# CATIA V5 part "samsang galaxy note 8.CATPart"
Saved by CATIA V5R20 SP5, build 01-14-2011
Part number: Part1
Material "Black": density 7860 kg/m3, Young's modulus 2e+11 Pa, Poisson ratio 0.266
Bounding box of the stored display mesh (mm): x -4.4 to 4.3, y -38.2 to 38.2, z -81.25 to 81.25
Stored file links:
  E:\180212220\创新作业180212220\samsang galaxy note 8.CATPart
  C:\Program Files\Dassault Systemes\B20\intel_a\startup\materials\Catalog.CATMaterial
  C:\Program Files\Dassault Systemes\B20\intel_a\startup\materials\black_env_512x512.jpg
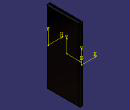
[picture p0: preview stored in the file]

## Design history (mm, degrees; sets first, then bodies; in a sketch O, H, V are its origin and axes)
Body1 (main body), material "Black"
  Sketch1 on yz-plane, origin (0, 0, 0), H (0, 1, 0), V (0, 0, 1)
    line L1 (37.4, 81.25) -> (37.4, -81.25)
    line L2 (37.4, -81.25) -> (-37.4, -81.25)
    line L3 (-37.4, -81.25) -> (-37.4, 81.25)
    line L4 (-37.4, 81.25) -> (37.4, 81.25)
    length L4 = 74.8
    length L1 = 162.5
    vertical: L1 V, L3 V
    horizontal: L2 H, L4 H
    equidistance: L1 L3 O, L2 L4 O
  Pad1: profile Sketch1, direction (1, 0, 0), length 4.3, mirrored extent
  Fillet1: radius 2.5, on end face of Pad1; face of Pad1 from Sketch1.L1; start face of Pad1; face of Pad1 from Sketch1.L3
  Plane1: type Offset, RefPlane yz-plane, Offset 4.3
  Plane2: type Offset, RefPlane yz-plane, Offset 4.3, reversed
  Plane3: type Offset, RefPlane zx-plane, Offset 37.4
  Plane4: type Offset, RefPlane zx-plane, Offset 37.4, reversed
  Plane5: type Offset, RefPlane xy-plane, Offset 81.25
  Plane6: type Offset, RefPlane xy-plane, Offset 81.25, reversed
  Sketch2 on Plane6, origin (0, 0, -81.25), H (1, 0, 0), V (0, 1, 0)
    construction line L1 (0, 2.9) -> (0, -2.9)
    point P1 (0, 2.9)
    line L2 (1.25, 2.9) -> (1.25, -2.9)
    line L3 (-1.25, -2.9) -> (-1.25, 2.9)
    arc A1 centre (0, -2.9) radius 1.25 from (1.25, -2.9) to (-1.25, -2.9) cw
    arc A2 centre (0, 2.9) radius 1.25 from (-1.25, 2.9) to (1.25, 2.9) cw
    line L4 (0.5, 2.5) -> (0.5, -2.5)
    line L5 (0.5, -2.5) -> (-0.5, -2.5)
    line L6 (-0.5, -2.5) -> (-0.5, 2.5)
    line L7 (-0.5, 2.5) -> (0.5, 2.5)
    distance P1 H = 2.9
    length L1 = 5.8
    distance L1 L2 = 1.25
    length L7 = 1
    length L4 = 5
    coincidence: P1 V
    vertical: L1 V, L4 V, L6 V
    tangency: A1 L2, A2 L2, A1 L3, A2 L3
    horizontal: L5 H, L7 H
    equidistance: L4 L6 O, L5 L7 O
  Pocket1: profile Sketch2, direction (0, 0, 1), length 6
  Sketch3 on Plane1, origin (4.3, 0, 0), H (0, 1, 0), V (0, 0, 1)
    construction line L1 (-3.5, 75) -> (3.5, 75)
    point P1 (-3.5, 75)
    line L2 (-3.5, 75.5) -> (3.5, 75.5)
    line L3 (3.5, 74.5) -> (-3.5, 74.5)
    arc A1 centre (3.5, 75) radius 0.5 from (3.5, 75.5) to (3.5, 74.5) cw
    arc A2 centre (-3.5, 75) radius 0.5 from (-3.5, 74.5) to (-3.5, 75.5) cw
    circle A3 centre (15, 75) radius 1.5
    point P7 (15, 75)
    circle A4 centre (20, 75) radius 1
    point P8 (20, 75)
    distance P1 V = 3.5
    distance P1 H = 75
    length L1 = 7
    distance L1 L2 = 0.5
    distance P7 H = 75
    distance P7 V = 15
    radius A3 = 1.5
    distance P8 H = 75
    radius A4 = 1
    horizontal: L1 H
    tangency: A1 L2, A2 L2, A1 L3, A2 L3
  Pocket2: profile Sketch3, direction (-1, 0, 0), length 0.2
  Plane7: type Offset, RefPlane Plane6, Offset 5
  Sketch4 on Plane6, origin (0, 0, -81.25), H (1, 0, 0), V (0, 1, 0)
    circle A1 centre (0, -25) radius 1.75
    point P1 (0, -25)
    distance P1 V = 0
    distance P1 H = 25
    radius A1 = 1.75
  Sketch5 on Plane7, origin (0, 0, -76.25), H (1, 0, 0), V (0, 1, 0)
    circle A1 centre (0, -25) radius 1.05
    point P1 (0, -25)
    distance P1 V = 0
    distance P1 H = 25
    radius A1 = 1.05
  Pocket3: profile Sketch4, direction (0, 0, 1), length 5
  Pocket4: profile Sketch5, direction (0, 0, 1), length 3
  Sketch6 on Plane3, origin (0, 37.4, 0), H (-1, 0, 0), V (0, 0, 1)
    construction line L1 (0, 20) -> (0, 28)
    point P1 (0, 20)
    line L2 (-0.6, 20) -> (-0.6, 28)
    line L3 (0.6, 28) -> (0.6, 20)
    arc A1 centre (0, 28) radius 0.6 from (-0.6, 28) to (0.6, 28) cw
    arc A2 centre (0, 20) radius 0.6 from (0.6, 20) to (-0.6, 20) cw
    length L1 = 8
    distance L1 L2 = 0.6
    distance H P1 = 20
    coincidence: P1 V
    vertical: L1 V
    tangency: A1 L2, A2 L2, A1 L3, A2 L3
  Sketch7 on Plane3, origin (0, 37.4, 0), H (-1, 0, 0), V (0, 0, 1)
  Sketch8 on Plane3, origin (0, 37.4, 0), H (-1, 0, 0), V (0, 0, 1)
  Pad2: profile Sketch6, direction (0, 1, 0), length 0.8
  Sketch9 on Plane4, origin (0, -37.4, 0), H (-1, 0, 0), V (0, 0, 1)
    construction line L1 (0, 13) -> (0, 21)
    point P1 (0, 13)
    line L2 (-0.6, 13) -> (-0.6, 21)
    line L3 (0.6, 21) -> (0.6, 13)
    arc A1 centre (0, 21) radius 0.6 from (-0.6, 21) to (0.6, 21) cw
    arc A2 centre (0, 13) radius 0.6 from (0.6, 13) to (-0.6, 13) cw
    construction line L4 (0, 30) -> (0, 50)
    point P7 (0, 30)
    line L5 (-0.6, 30) -> (-0.6, 50)
    line L6 (0.6, 50) -> (0.6, 30)
    arc A3 centre (0, 50) radius 0.6 from (-0.6, 50) to (0.6, 50) cw
    arc A4 centre (0, 30) radius 0.6 from (0.6, 30) to (-0.6, 30) cw
    distance L1 L2 = 0.6
    distance H P1 = 13
    length L1 = 8
    distance L4 L5 = 0.6
    length L4 = 20
    distance H P7 = 30
    coincidence: P1 V, P7 V
    vertical: L1 V, L4 V
    tangency: A1 L2, A2 L2, A1 L3, A2 L3, A3 L5, A4 L5, A3 L6, A4 L6
  Sketch10 on Plane4, origin (0, -37.4, 0), H (-1, 0, 0), V (0, 0, 1)
  Sketch11 on Plane4, origin (0, -37.4, 0), H (-1, 0, 0), V (0, 0, 1)
  Sketch12 on Plane4, origin (0, -37.4, 0), H (-1, 0, 0), V (0, 0, 1)
  Pad3: profile Sketch9, direction (0, -1, 0), length 0.8
  Sketch13 on Plane2, origin (-4.3, 0, 0), H (0, 1, 0), V (0, 0, 1)
    point P1 (0, 55)
    line L1 (22.5, 61) -> (22.5, 49)
    line L2 (19.5, 46) -> (-19.5, 46)
    line L3 (-22.5, 49) -> (-22.5, 61)
    line L4 (-19.5, 64) -> (19.5, 64)
    arc A1 centre (19.5, 49) radius 3 from (19.5, 46) to (22.5, 49) ccw
    arc A2 centre (-19.5, 49) radius 3 from (-22.5, 49) to (-19.5, 46) ccw
    arc A3 centre (-19.5, 61) radius 3 from (-22.5, 61) to (-19.5, 64) cw
    arc A4 centre (19.5, 61) radius 3 from (19.5, 64) to (22.5, 61) cw
    line L5 (21.5, 60) -> (21.5, 50)
    line L6 (18.5, 47) -> (-18.5, 47)
    line L7 (-21.5, 50) -> (-21.5, 60)
    line L8 (-18.5, 63) -> (18.5, 63)
    arc A5 centre (18.5, 60) radius 3 from (18.5, 63) to (21.5, 60) cw
    arc A6 centre (18.5, 50) radius 3 from (18.5, 47) to (21.5, 50) ccw
    arc A7 centre (-18.5, 50) radius 3 from (-21.5, 50) to (-18.5, 47) ccw
    arc A8 centre (-18.5, 60) radius 3 from (-21.5, 60) to (-18.5, 63) cw
    distance H P1 = 55
    radius A1 = 3
    radius A2 = 3
    radius A3 = 3
    radius A4 = 3
    radius A5 = 3
    radius A6 = 3
    radius A7 = 3
    radius A8 = 3
    coincidence: P1 V
    vertical: L1 V, L3 V, L5 V, L7 V
    horizontal: L2 H, L4 H, L6 H, L8 H
    equidistance: L1 L3 P1, L2 L4 P1, L5 L7 P1, L6 L8 P1
    tangency: A1 L2, A1 L1, A2 L3, A2 L2, A3 L3, A3 L4, A4 L4, A4 L1, A5 L8, A5 L5, A6 L6, A6 L5, A7 L7, A7 L6, A8 L7, A8 L8
  Pad4: profile Sketch13, direction (-1, 0, 0), length 0.1
  Sketch14 on Plane2, origin (-4.3, 0, 0), H (0, 1, 0), V (0, 0, 1)
    circle A1 centre (13, 55) radius 2.5
    point P1 (13, 55)
    circle A2 centre (3, 55) radius 2.5
    point P2 (3, 55)
    point P3 (-15, 55)
    line L1 (-11, 60) -> (-11, 50)
    line L2 (-13, 48) -> (-17, 48)
    line L3 (-19, 50) -> (-19, 60)
    line L4 (-17, 62) -> (-13, 62)
    arc A3 centre (-17, 60) radius 2 from (-17, 62) to (-19, 60) ccw
    arc A4 centre (-13, 60) radius 2 from (-13, 62) to (-11, 60) cw
    arc A5 centre (-17, 50) radius 2 from (-19, 50) to (-17, 48) ccw
    arc A6 centre (-13, 50) radius 2 from (-11, 50) to (-13, 48) cw
    point P16 (-5, 59)
    line L5 (-3.5, 60) -> (-3.5, 58)
    line L6 (-4, 57.5) -> (-6, 57.5)
    line L7 (-6.5, 58) -> (-6.5, 60)
    line L8 (-6, 60.5) -> (-4, 60.5)
    arc A7 centre (-6, 60) radius 0.5 from (-6.5, 60) to (-6, 60.5) cw
    arc A8 centre (-4, 60) radius 0.5 from (-3.5, 60) to (-4, 60.5) ccw
    arc A9 centre (-6, 58) radius 0.5 from (-6.5, 58) to (-6, 57.5) ccw
    arc A10 centre (-4, 58) radius 0.5 from (-4, 57.5) to (-3.5, 58) ccw
    point P29 (-10, 50)
    distance H P1 = 55
    distance V P1 = 13
    radius A1 = 2.5
    radius A2 = 2.5
    distance P2 H = 55
    distance P2 V = 3
    distance P3 V = 15
    distance P3 H = 55
    radius A3 = 2
    radius A4 = 2
    radius A5 = 2
    radius A6 = 2
    distance V P16 = 5
    distance P16 H = 59
    radius A7 = 0.5
    radius A8 = 0.5
    radius A9 = 0.5
    radius A10 = 0.5
    distance P29 H = 50
    distance V P29 = 10
    length L5 = 2
    length L6 = 2
    vertical: L1 V, L3 V, L5 V, L7 V
    horizontal: L2 H, L4 H, L6 H, L8 H
    equidistance: L1 L3 P3, L2 L4 P3, L5 L7 P16, L6 L8 P16
    tangency: A3 L4, A3 L3, A4 L4, A4 L1, A5 L3, A5 L2, A6 L1, A6 L2, A7 L7, A7 L8, A8 L5, A8 L8, A9 L7, A9 L6, A10 L6, A10 L5
  Sketch15 on Plane2, origin (-4.3, 0, 0), H (0, 1, 0), V (0, 0, 1)
  Pad5: profile Sketch14, direction (-1, 0, 0), length 0.1
  Sketch16 on Plane6, origin (0, 0, -81.25), H (1, 0, 0), V (0, 1, 0)
    construction line L1 (0, 28.5) -> (0, 26)
    point P1 (0, 28.5)
    point P2 (0, 26)
    line L2 (1.5, 28.5) -> (1.5, 26)
    line L3 (-1.5, 26) -> (-1.5, 28.5)
    arc A1 centre (0, 26) radius 1.5 from (1.5, 26) to (-1.5, 26) cw
    arc A2 centre (0, 28.5) radius 1.5 from (-1.5, 28.5) to (1.5, 28.5) cw
    distance L1 L2 = 1.5
    length L1 = 2.5
    distance H P2 = 26
    coincidence: P1 V
    vertical: L1 V
    tangency: A1 L2, A2 L2, A1 L3, A2 L3
  Pocket5: profile Sketch16, direction (0, 0, 1), length 110
Body2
